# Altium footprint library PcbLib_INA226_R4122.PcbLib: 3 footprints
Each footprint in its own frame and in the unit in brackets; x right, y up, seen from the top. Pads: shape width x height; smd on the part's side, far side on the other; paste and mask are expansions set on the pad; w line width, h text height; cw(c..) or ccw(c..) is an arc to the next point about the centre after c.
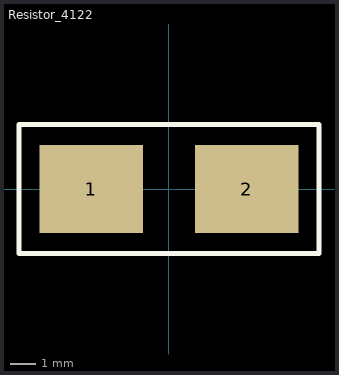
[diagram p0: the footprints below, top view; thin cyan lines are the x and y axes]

## PCBComponent_1 [mm]
M5 Assembly Top:
  text ".Designator" at -1.524,-0.508 h1.02

## PCBComponent_1 - duplicate [mm]

## Resistor_4122 [mm]
pads (2):
  rect 4x3.4 smd: 1(-3,0) 2(3,0)
Top Overlay:
  lines w0.2: -5.8,-2.5 -5.8,0 -5.8,2.5 5.8,2.5 5.8,-2.5 -5.8,-2.5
